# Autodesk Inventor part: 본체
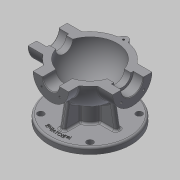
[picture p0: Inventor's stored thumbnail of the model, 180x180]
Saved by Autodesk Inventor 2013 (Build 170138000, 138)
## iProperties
Created: 2015-12
Part Number: 본체
Material: 일반
Document SubType Name: Modeling
Designer: mduedu
Density: 2.71 g/cm^3
Author: mduedu
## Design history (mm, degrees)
sketch "스케치1"
  geometry: L1 (-53, 0)-(53, 0); A1 r 53 centre (0, 0) between (53, 0) and (-53, 0); 2 further points
  constraints: 2 coincident, 2 end point, 2 point on circle, 1 centre point, 1 horizontal, 1 midpoint
  dimensions: "d0" = 53 radius of A1
revolve "회전1" sketch "스케치1" stored, may be unused: angle "d2" = 90 deg
feature "쉘1" dims "d11" = 10
node "작업 평면1"
sketch "스케치2"
  geometry: C1 r 31 at (0, 0); 1 further point
  constraints: 1 centre point, 1 coincident
  dimensions: "d4" = 62 diameter of C1
extrude "돌출1" join sketch "스케치2" stored distance "d5" = 10; taper "d6" = 0 deg
node "작업 평면2"
sketch "스케치3"
  geometry: C1 r 28 at (0, 0); 1 further point
  constraints: 1 centre point, 1 coincident
  dimensions: "d8" = 56 diameter of C1
extrude "돌출2" join sketch "스케치3" stored distance "d9" = 10; taper "d10" = 0 deg
hole "구멍1" diameter "d14" = 35; stored, may be unused: countersink angle "d18" = 90 deg, drill point angle "d20" = 0 deg; dims "d12" = 10, "d13" = 10, "d15" = 6, "d16" = 4, "d17" = 2, "d19" = 16
hole "구멍2" diameter "d23" = 27; stored, may be unused: countersink angle "d27" = 90 deg, drill point angle "d29" = 0 deg; dims "d21" = 10, "d22" = 10, "d24" = 6, "d25" = 4, "d26" = 2, "d28" = 16
fillet "모깎기1" dims "d30" = 0.3
hole "구멍3" diameter "d33" = 26; stored, may be unused: countersink angle "d37" = 90 deg, drill point angle "d39" = 0 deg; dims "d31" = 10, "d32" = 10, "d34" = 6, "d35" = 4, "d36" = 2, "d38" = 16
chamfer "모따기1" distance "d40" = 1; stored, may be unused: second distance "d41" = 2, angle "d42" = 45 deg
sketch "스케치4"
  geometry: L1 (0, 0)-(0, -25); L2 (0, 0)-(-17.678, -17.678); A1 r 25 centre (0, 0) between (-17.678, -17.678) and (0, -25); 1 further point
  constraints: 4 end point, 2 point on circle, 1 centre point, 1 coincident, 1 vertical
  dimensions: "d43" = 50 diameter of A1; "d47" = 45 deg angle of L1 L2
hole "구멍4" sketch "스케치4" at (-17.678, -17.678) diameter "d49" = 3.242; stored, may be unused: countersink angle "d53" = 90 deg, drill point angle "d55" = 118 deg; dims "d50" = 11, "d51" = 4, "d52" = 2, "d54" = 13
sketch "스케치5"
  geometry: L1 (0, 0)-(0, -20); L2 (0, 0)-(-14.142, -14.142); A1 r 20 centre (0, 0) between (0, -20) and (-14.142, -14.142); 2 further points
  constraints: 4 end point, 2 coincident, 2 point on circle, 1 centre point, 1 vertical
  dimensions: "d59" = 40 diameter of A1; "d65" = 45 deg angle of L1 L2
hole "구멍5" sketch "스케치5" at (-14.142, -14.142) diameter "d67" = 3.242; stored, may be unused: countersink angle "d71" = 90 deg, drill point angle "d73" = 118 deg; dims "d68" = 8, "d69" = 4, "d70" = 2, "d72" = 10
node "작업 평면3"
sketch "스케치6"
  geometry: C1 r 65 at (0, 0); 1 further point
  constraints: 1 centre point, 1 coincident
  dimensions: "d78" = 130 diameter of C1
extrude "돌출3" join sketch "스케치6" distance "d80" = 10; taper "d81" = 0 deg
sketch "스케치7"
  geometry: C1 r 20 at (0, 0); 1 further point
  constraints: 1 centre point, 1 coincident
  dimensions: "d82" = 40 diameter of C1
extrude "돌출4" join sketch "스케치7" stored distance "d84" = 10; taper "d85" = 0 deg
sketch "스케치8"
  geometry: 2 further points
  constraints: 1 coincident
hole "구멍6" sketch "스케치8" at (0, 0) diameter "d86" = 20; stored, may be unused: countersink angle "d90" = 90 deg, drill point angle "d92" = 118 deg; dims "d87" = 7, "d88" = 40, "d89" = 5, "d91" = 10
fillet "모깎기2" dims "d93" = 0.3
sketch "스케치9"
  geometry: L1 (65, -75)-(-65, -75) reference; L2 (-45, -75)-(-38.245, -36.692); A1 r 53 centre (0, 0) between (42.988, 31) and (42.988, -31) reference; 1 further point
  constraints: 2 end point, 1 point on circle, 1 point on line
  dimensions: "d94" = 45 horizontal distance of L2.start point (0, 0); "d95" = 80 deg angle of L2 L1
feature "리브1" sketch "스케치9" dims "d96" = 1, "d97" = 8, "d98" = 0, "d99" = 0, "d100" = 1, "d101" = 1
sketch "스케치10"
  geometry: L1 (0, 0)-(0, -55); L2 (0, 0)-(-38.891, -38.891); A1 r 55 centre (0, 0) between (0, -55) and (-38.891, -38.891); 2 further points
  constraints: 4 end point, 2 coincident, 2 point on circle, 1 centre point, 1 vertical
  dimensions: "d105" = 110 diameter of A1; "d107" = 45 deg angle of L1 L2
hole "구멍7" sketch "스케치10" at (-38.891, -38.891) diameter "d109" = 10; stored, may be unused: countersink angle "d113" = 90 deg, drill point angle "d115" = 118 deg; dims "d110" = 7, "d111" = 40, "d112" = 5, "d114" = 10
fillet "모깎기3" dims "d120" = 3
fillet "모깎기4" dims "d121" = 3, "d122" = 3
fillet "모깎기5" dims "d123" = 3
fillet "모깎기6" dims "d124" = 3
sketch "스케치11"
  geometry: C1 r 5 at (-38.891, 38.891) reference; C2 r 5 at (38.891, 38.891) reference; C3 r 5 at (38.891, -38.891) reference; C4 r 5 at (-38.891, -38.891) reference; C5 r 20 at (0, 0) reference; C6 r 65 at (0, 0) reference; 1 further point
  constraints: 3 other
feature "엠보싱1" sketch "스케치11" dims "d125" = 0.5, "d126" = 0
sketch "스케치12"
  geometry: L1 (0, 100)-(0, -100); L2 (0, 100)-(100, 100); L3 (100, 100)-(100, -100); L4 (100, -100)-(0, -100); 2 further points
  constraints: 8 end point, 3 perpendicular, 1 coincident, 1 midpoint, 1 vertical
  dimensions: "d127" = 200 distance of L2.end L3.end; "d129" = 100 distance between parallel lines of L1 L3
extrude "돌출5" cut sketch "스케치12" stored distance "d130" = 10; taper "d131" = 0 deg
sketch "스케치13"
  geometry: C1 r 7 at (0, 53); A1 r 53 centre (0, 0) between (42.113, 32.179) and (-42.113, 32.179) reference; 1 further point
  constraints: 1 centre point, 1 point on circle
  dimensions: "d132" = 14 diameter of C1
extrude "돌출6" join sketch "스케치13" distance "d134" = 15; taper "d135" = 0 deg
hole "구멍8" diameter "d139" = 3.242; stored, may be unused: countersink angle "d143" = 90 deg, drill point angle "d145" = 118 deg; dims "d140" = 8, "d141" = 4, "d142" = 2, "d144" = 10, "d148" = 10, "d149" = 10
fillet "모깎기7" dims "d146" = 3
fillet "모깎기8" dims "d147" = 3
node "솔리드1"
mirror "대칭1"
mirror "대칭2"
pattern_circular "원형 패턴1" dims angle "d57" = 360 deg
mirror "대칭3"
pattern_circular "원형 패턴2" dims angle "d75" = 360 deg
pattern_circular "원형 패턴3" dims angle "d103" = 360 deg
pattern_circular "원형 패턴4" dims angle "d118" = 360 deg
node "투영된 루프1"
other parameters: "d3" = 67, "d7" = 62, "d77" = -85
